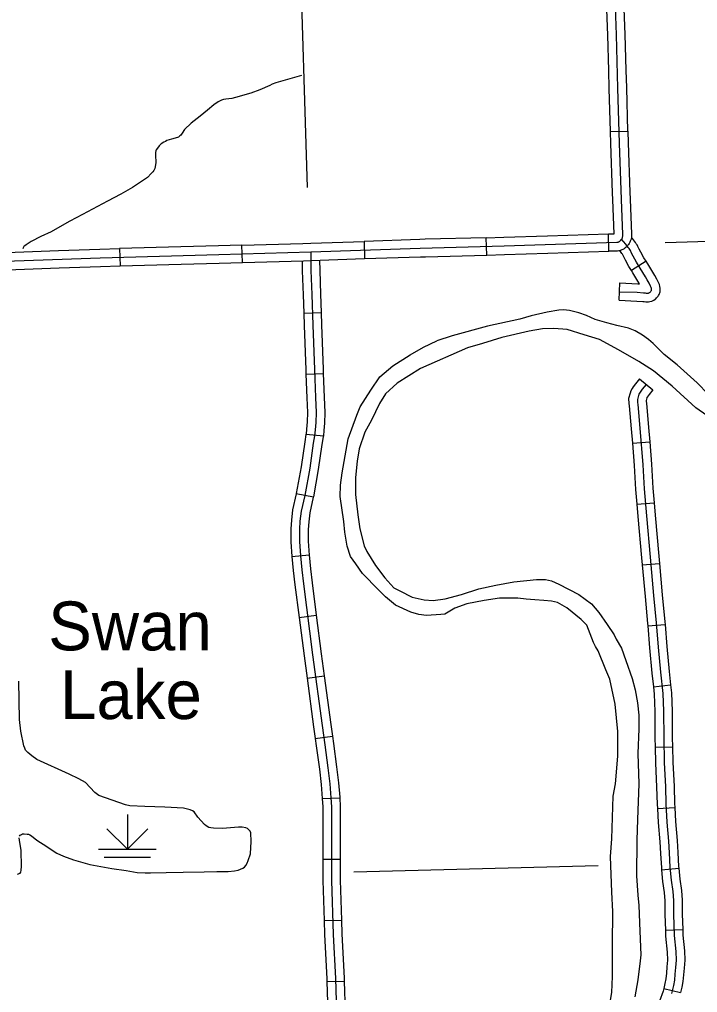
# Model space of a CAD drawing. Extents: x 1720274 to 1751788, y 372074 to 391887.
# Drawn here: x 1738121 to 1739046, y 375342 to 376671 of the extents above; entities that cross this region are included whole.
import ezdxf

# ---------------------------------------------------------------- set-up
doc = ezdxf.new("R2010")
doc.units = 0
for name, color, linetype in [('Level 31', 7, 'Continuous'), ('Level 32', 7, 'Continuous'), ('Level 35', 7, 'Continuous'), ('Level 44', 7, 'Continuous'), ('Level 47', 7, 'Continuous'), ('Level 5', 7, 'Continuous'), ('Level 9', 7, 'Continuous')]:
    doc.layers.add(name, color=color, linetype=linetype)

msp = doc.modelspace()

# ---------------------------------------------------------------- linework, layer by layer
at = {"layer": 'Level 31'}
for p, q in [((1738927.4, 376517.8), (1738951.1, 376518.4)), ((1738758.5, 376349.2), (1738757.9, 376372.9)), ((1738925.3, 376354.4), (1738924.6, 376378.1)), ((1738425, 376339.1), (1738424.3, 376362.8)), ((1738591, 376367.9), (1738591.8, 376344.3)), ((1738257.5, 376358.1), (1738258.2, 376334.4)), ((1738258.2, 376334.4), (1738258.2, 376334.4)), ((1738591.8, 376344.3), (1738591.8, 376344.3))]:
    msp.add_line(p, q, dxfattribs=at)
for points in [[(1738942.4, 376370.7), (1738942.6, 376370.9), (1738943, 376371.5), (1738943.3, 376371.9), (1738943.6, 376372.6), (1738943.8, 376373.1), (1738944, 376373.9), (1738944.2, 376374.8), (1738944.2, 376375.6), (1738944.2, 376377.2), (1738942.5, 376425), (1738939.8, 376501.9), (1738937.6, 376577.2), (1738935.7, 376650.1), (1738933.7, 376701.6), (1738933.4, 376704), (1738933.2, 376706), (1738933, 376707.8), (1738932.7, 376710), (1738932.3, 376712.2), (1738931.7, 376714.6), (1738930.9, 376717.1), (1738930.6, 376718.4)], [(1738925.1, 376601.2), (1738923.9, 376649.7), (1738922.5, 376684.4)], [(1738948.8, 376601.8), (1738947.5, 376650.5), (1738946.2, 376685.3)], [(1738927.4, 376517.8), (1738925.8, 376576.9), (1738925.1, 376601.2)], [(1738951.1, 376518.4), (1738949.5, 376577.5), (1738948.8, 376601.8)], [(1738930.3, 376434.3), (1738927.9, 376501.5), (1738927.4, 376517.8)], [(1738951.1, 376518.4), (1738951.6, 376502.3), (1738954, 376435.1)], [(1738924.6, 376378.1), (1738932.3, 376378.3), (1738930.6, 376424.6), (1738930.3, 376434.3)], [(1738954, 376435.1), (1738954.3, 376425.4), (1738956, 376377.6), (1738956.1, 376375.4), (1738956, 376373.4), (1738955.6, 376371.1), (1738954.9, 376368.9), (1738954.4, 376368), (1738954, 376366.9), (1738953.1, 376365.2), (1738951.9, 376363.5), (1738951.2, 376362.7), (1738951.1, 376362.6), (1738951, 376362.5), (1738950.4, 376361.8), (1738949, 376360.2), (1738947.6, 376359), (1738946, 376357.8), (1738944.2, 376356.9), (1738942.9, 376356.2), (1738942.1, 376355.9), (1738941.2, 376355.5), (1738940.6, 376355.4), (1738940, 376355.2), (1738938.7, 376354.9), (1738936.9, 376354.7), (1738925.3, 376354.4)], [(1738757.9, 376372.9), (1738674.5, 376370.7)], [(1738757.9, 376372.9), (1738781.9, 376373.6), (1738841.2, 376375.4)], [(1738841.2, 376375.4), (1738924.6, 376378.1)], [(1738340.9, 376360.5), (1738257.5, 376358.1)], [(1738424.3, 376362.8), (1738392.4, 376361.9), (1738340.9, 376360.5)], [(1738424.3, 376362.8), (1738507.7, 376365.2)], [(1738507.7, 376365.2), (1738518.2, 376365.5), (1738591, 376367.9)], [(1738518.5, 376353.7), (1738667.7, 376358.7), (1738782.2, 376361.7), (1738936.1, 376366.6), (1738936.8, 376366.6)], [(1738674.5, 376370.7), (1738667.3, 376370.5), (1738591, 376367.9)], [(1738936.8, 376366.6), (1738937.1, 376366.7), (1738937.3, 376366.8), (1738937.5, 376366.8), (1738937.7, 376366.9), (1738938.1, 376367.1), (1738938.9, 376367.4), (1738939.6, 376367.8), (1738940.2, 376368.2), (1738940.7, 376368.7), (1738941.4, 376369.4), (1738941.7, 376369.9), (1738942.1, 376370.4), (1738942.4, 376370.7)], [(1737257.5, 376308.3), (1737305.2, 376310.2), (1737378.2, 376313.6), (1737446.6, 376316.8), (1737514.4, 376319.4), (1737666.2, 376325.4), (1737815.1, 376331.2), (1737916, 376335.2), (1738087.5, 376340.4), (1738231, 376345.5), (1738392.8, 376350.1), (1738518.5, 376353.7)], [(1738090.7, 376352.4), (1738174.1, 376355.3)], [(1738174.1, 376355.3), (1738230.6, 376357.4), (1738257.5, 376358.1)], [(1738591.8, 376344.3), (1738668, 376346.8), (1738675.1, 376347)], [(1738675.1, 376347), (1738758.5, 376349.2)], [(1738758.5, 376349.2), (1738782.6, 376349.9), (1738842, 376351.7)], [(1738842, 376351.7), (1738925.3, 376354.4)], [(1738174.9, 376331.7), (1738231.3, 376333.7), (1738258.2, 376334.4)], [(1738258.2, 376334.4), (1738341.6, 376336.8)], [(1738341.6, 376336.8), (1738393.1, 376338.2), (1738425, 376339.1)], [(1738425, 376339.1), (1738508.4, 376341.5)], [(1738508.4, 376341.5), (1738518.9, 376341.8), (1738591.8, 376344.3)], [(1738091.6, 376328.7), (1738174.9, 376331.7)]]:
    msp.add_lwpolyline(points, dxfattribs=at)
at = {"layer": 'Level 32'}
for p, q in [((1738975.9, 376340.8), (1738956, 376328)), ((1738939.2, 376287.4), (1738940.1, 376311.1)), ((1738508.9, 376269.9), (1738532.5, 376270.7)), ((1738511.7, 376186.5), (1738535.4, 376187.3)), ((1738967.2, 376180.2), (1738985.3, 376165)), ((1738511.9, 376104.7), (1738535.5, 376102.4)), ((1738957.3, 376092.2), (1738981, 376094.1)), ((1738498.6, 376023.4), (1738521.9, 376019.2)), ((1738963.2, 376009), (1738986.9, 376010.9)), ((1738492.5, 375937.4), (1738516.1, 375939.7)), ((1738970.8, 375925.9), (1738994.4, 375927.9)), ((1738502.3, 375854.2), (1738525.8, 375857.2)), ((1738978.3, 375842.8), (1739001.9, 375844.8)), ((1738513.2, 375771.4), (1738536.7, 375774.6)), ((1738985.9, 375759.5), (1739009.5, 375762)), ((1738524.4, 375688.7), (1738547.9, 375692)), ((1738988.4, 375677.1), (1739012.1, 375677.6)), ((1738534.1, 375607), (1738557.8, 375608.1)), ((1738991.5, 375593.4), (1739015.2, 375594.6)), ((1738534.8, 375524.1), (1738558.5, 375524.1)), ((1738997, 375509.6), (1739020.6, 375512)), ((1738536.5, 375440.4), (1738560.2, 375441)), ((1739002.3, 375427.3), (1739026, 375428)), ((1738540.2, 375357), (1738563.9, 375357.7)), ((1739000, 375347.6), (1739023, 375341.9))]:
    msp.add_line(p, q, dxfattribs=at)
for points in [[(1738975.9, 376340.8), (1738972.9, 376345.4), (1738968.9, 376353.1), (1738966.7, 376357.3), (1738964.9, 376361.1), (1738963.6, 376363.3), (1738962.6, 376364.7), (1738961.5, 376366.3), (1738960.3, 376368), (1738957.5, 376371.6), (1738955.9, 376373.3)], [(1738939.6, 376299.2), (1738963.9, 376298.3), (1738972.4, 376297.6), (1738974.6, 376297.4), (1738976.3, 376297.2), (1738977.1, 376297.2), (1738977.9, 376297.3), (1738978.5, 376297.3), (1738979.1, 376297.3), (1738979.9, 376297.5), (1738980.4, 376297.7), (1738980.8, 376298), (1738981.4, 376298.6), (1738982, 376299.1), (1738982.6, 376299.8), (1738983, 376300.3), (1738983.2, 376300.7), (1738983.4, 376301.3), (1738983.4, 376301.7), (1738983.4, 376302.2), (1738983.4, 376302.7), (1738983.3, 376303.6), (1738982.9, 376304.8), (1738982.1, 376306.7), (1738980, 376310.8), (1738977.6, 376315.5), (1738975, 376319.6), (1738968.1, 376331.1), (1738962.7, 376339.4), (1738958.4, 376347.6), (1738956.1, 376352), (1738954.5, 376355.4), (1738953.7, 376356.7), (1738952.8, 376358), (1738951.7, 376359.6), (1738950.8, 376361), (1738948.4, 376363.9), (1738945.1, 376367.5), (1738942.4, 376370.7)], [(1738518.5, 376353.7), (1738518.6, 376328), (1738519.8, 376295.2), (1738521.3, 376253.4), (1738523.3, 376192.8), (1738524.7, 376154.5), (1738525.7, 376134.1), (1738525.1, 376120.5)], [(1738956, 376328), (1738952.5, 376333.4), (1738947.9, 376342.1), (1738945.5, 376346.8), (1738944.1, 376349.7), (1738943.8, 376350.2), (1738943.1, 376351.2), (1738942, 376352.8), (1738941.2, 376353.9), (1738940.1, 376355.3)], [(1738506.7, 376341.5), (1738506.8, 376327.8), (1738508, 376294.8), (1738508.9, 376269.9)], [(1738530.4, 376342.2), (1738530.5, 376328.2), (1738531.7, 376295.7), (1738532.5, 376270.7)], [(1738939.2, 376287.4), (1738963.2, 376286.4), (1738971.4, 376285.8), (1738973.5, 376285.6), (1738975.7, 376285.4), (1738977.5, 376285.4), (1738978.3, 376285.4), (1738979.1, 376285.4), (1738980.9, 376285.6), (1738983.6, 376286.1), (1738986.4, 376287.4), (1738988.4, 376288.9), (1738989.2, 376289.6), (1738990.4, 376290.7), (1738992.3, 376292.9), (1738992.9, 376293.8), (1738994, 376295.4), (1738995, 376298.8), (1738995.3, 376301), (1738995.3, 376302.2), (1738995.3, 376303.8), (1738994.8, 376306.4), (1738994.1, 376308.8), (1738992.9, 376311.6), (1738990.6, 376316.2), (1738987.9, 376321.5), (1738985, 376325.9), (1738978.2, 376337.3), (1738975.9, 376340.8)], [(1738940.1, 376311.1), (1738964.6, 376310.1), (1738967.1, 376309.9), (1738964.9, 376313.4), (1738958, 376324.8), (1738956, 376328)], [(1738508.9, 376269.9), (1738509.5, 376253), (1738511.5, 376192.4), (1738511.7, 376186.5)], [(1738532.5, 376270.7), (1738533.1, 376253.8), (1738535.2, 376193.3), (1738535.4, 376187.3)], [(1738535.4, 376187.3), (1738536.5, 376155), (1738537.6, 376134.2), (1738536.9, 376119.8), (1738536.2, 376109.6), (1738535.5, 376102.4)], [(1738511.7, 376186.5), (1738512.9, 376154), (1738513.9, 376134.1), (1738513.3, 376121.2), (1738512.6, 376111.6), (1738511.9, 376104.7)], [(1738967.2, 376180.2), (1738961.4, 376173.4), (1738958.3, 376169.1), (1738956.8, 376167.1), (1738955, 376163.7), (1738954.2, 376160.8), (1738952.2, 376153.3), (1738952.4, 376146.4), (1738953.1, 376143.3), (1738955.7, 376111.9), (1738957.3, 376092.2)], [(1738976.2, 376172.6), (1738970.8, 376166.1), (1738967.8, 376162.1), (1738966.9, 376160.8), (1738966.1, 376159.3), (1738965.6, 376157.6), (1738964.1, 376151.9), (1738964.2, 376147.9), (1738964.9, 376145.1), (1738967.5, 376112.9), (1738971.6, 376062.6), (1738973.4, 376029.9), (1738976.4, 375992.9), (1738981.7, 375936.7), (1738986.3, 375884.1), (1738989.9, 375847.1), (1738992.6, 375813.6), (1738995.7, 375779.4), (1738998.8, 375750.2), (1738999.8, 375726.1), (1739000, 375690), (1739000.7, 375656.2), (1739002.3, 375623), (1739003, 375599.5), (1739004.3, 375574.8), (1739006.4, 375548.8), (1739007.7, 375532.7), (1739008.6, 375513), (1739010.4, 375495.2), (1739012.5, 375480), (1739013.4, 375467.6), (1739013.4, 375448.6), (1739014.4, 375419.8), (1739016.4, 375398.1), (1739016.9, 375386.2), (1739016.3, 375376), (1739015.4, 375367.1), (1739014.6, 375358.7), (1739013.2, 375351.6), (1739010.5, 375340.6)], [(1738985.3, 376165), (1738980.1, 376158.7), (1738977.3, 376155), (1738977.1, 376154.7), (1738977, 376154.4), (1738976, 376150.6), (1738976, 376149.4), (1738976.6, 376146.8), (1738979.3, 376113.9), (1738981, 376094.1)], [(1738525.1, 376120.5), (1738524.4, 376110.6), (1738523.6, 376102.5), (1738521.8, 376092.2), (1738516.9, 376058.2), (1738510.2, 376020.9), (1738505.3, 375999.3), (1738503.6, 375985.8), (1738502.9, 375974.8), (1738503, 375958.1), (1738504.3, 375938.6), (1738506.1, 375919.5), (1738508.3, 375900.1), (1738520.9, 375803.2), (1738533.9, 375706.6), (1738537.6, 375680.3), (1738541.8, 375648.7), (1738544.3, 375627.1), (1738545.9, 375607.8), (1738546.5, 375595.8), (1738546.4, 375584.3), (1738546.5, 375561), (1738546.7, 375535.6), (1738546.7, 375513), (1738546.8, 375495.1), (1738548.9, 375421.4), (1738551.9, 375361.1), (1738553.3, 375315.1)], [(1738511.9, 376104.7), (1738511.8, 376104.1), (1738510.1, 376094), (1738505.2, 376060.1), (1738498.6, 376023.4)], [(1738535.5, 376102.4), (1738535.3, 376101), (1738533.6, 376090.3), (1738528.6, 376056.3), (1738521.9, 376019.2)], [(1738981, 376094.1), (1738983.5, 376063.4), (1738985.3, 376030.7), (1738986.9, 376010.9)], [(1738957.3, 376092.2), (1738959.8, 376061.8), (1738961.6, 376029.1), (1738963.2, 376009)], [(1738498.6, 376023.4), (1738498.6, 376023.2), (1738493.6, 376001.3), (1738491.8, 375986.9), (1738491.1, 375975.2), (1738491.2, 375957.7), (1738492.4, 375937.6), (1738492.5, 375937.4)], [(1738521.9, 376019.2), (1738521.8, 376018.5), (1738517, 375997.2), (1738515.5, 375984.7), (1738514.8, 375974.5), (1738514.9, 375958.5), (1738516.1, 375939.5), (1738516, 375939.7)], [(1738963.2, 376009), (1738964.6, 375991.9), (1738969.9, 375935.7), (1738970.8, 375925.9)], [(1738986.9, 376010.9), (1738988.2, 375993.9), (1738993.5, 375937.8), (1738994.4, 375927.9)], [(1738492.5, 375937.4), (1738494.3, 375918.2), (1738496.5, 375898.7), (1738502.3, 375854.2)], [(1738516.1, 375939.7), (1738517.8, 375920.7), (1738520.1, 375901.6), (1738525.8, 375857.2)], [(1738970.8, 375925.9), (1738974.5, 375883), (1738978.1, 375846), (1738978.3, 375842.8)], [(1738994.4, 375927.9), (1738998.1, 375885.2), (1739001.7, 375848.2), (1739001.9, 375844.8)], [(1738525.8, 375857.2), (1738532.6, 375804.7), (1738536.7, 375774.6)], [(1738502.3, 375854.2), (1738509.1, 375801.6), (1738513.2, 375771.4)], [(1738978.3, 375842.8), (1738980.8, 375812.6), (1738983.9, 375778.2), (1738985.9, 375759.5)], [(1739001.9, 375844.8), (1739004.5, 375814.6), (1739007.5, 375780.5), (1739009.5, 375762)], [(1738536.7, 375774.6), (1738545.6, 375708.2), (1738547.9, 375692)], [(1738513.2, 375771.4), (1738522.2, 375705), (1738524.4, 375688.7)], [(1739009.5, 375762), (1739010.6, 375751.1), (1739011.7, 375726.3), (1739011.8, 375690.2), (1739012.1, 375677.6)], [(1738985.9, 375759.5), (1738987, 375749.4), (1738988, 375725.8), (1738988.1, 375689.9), (1738988.4, 375677.1)], [(1738524.4, 375688.7), (1738525.8, 375678.7), (1738530.1, 375647.2), (1738532.5, 375626), (1738534.1, 375607), (1738534.1, 375607)], [(1738547.9, 375692), (1738549.3, 375681.9), (1738553.6, 375650.2), (1738556.1, 375628.3), (1738557.8, 375608.6), (1738557.8, 375608.1)], [(1738988.4, 375677.1), (1738988.8, 375655.7), (1738990.4, 375622.6), (1738991.2, 375599), (1738991.5, 375593.4)], [(1739012.1, 375677.6), (1739012.5, 375656.6), (1739014.1, 375623.5), (1739014.9, 375600), (1739015.2, 375594.6)], [(1738534.1, 375607), (1738534.7, 375595.6), (1738534.6, 375584.3), (1738534.7, 375560.9), (1738534.8, 375535.6), (1738534.8, 375524.1)], [(1738557.8, 375608.1), (1738558.4, 375596.1), (1738558.3, 375584.3), (1738558.4, 375561), (1738558.5, 375535.7), (1738558.5, 375524.1)], [(1738991.5, 375593.4), (1738992.5, 375574), (1738994.6, 375547.9), (1738995.8, 375531.9), (1738996.8, 375512.2), (1738997, 375509.6)], [(1739015.2, 375594.6), (1739016.1, 375575.5), (1739018.3, 375549.8), (1739019.5, 375533.4), (1739020.4, 375513.9), (1739020.6, 375512)], [(1738534.8, 375524.1), (1738534.8, 375512.9), (1738534.9, 375494.9), (1738536.5, 375440.4)], [(1738558.5, 375524.1), (1738558.5, 375513), (1738558.6, 375495.4), (1738560.2, 375441)], [(1738997, 375509.6), (1738998.6, 375493.8), (1739000.7, 375478.7), (1739001.5, 375467.2), (1739001.6, 375448.4), (1739002.3, 375427.3)], [(1739020.6, 375512), (1739022.1, 375496.6), (1739024.3, 375481.2), (1739025.2, 375468), (1739025.3, 375448.9), (1739026, 375428)], [(1738536.5, 375440.4), (1738537, 375421), (1738540.1, 375360.6), (1738540.2, 375357)], [(1738560.2, 375441), (1738560.7, 375421.9), (1738563.8, 375361.6), (1738563.9, 375357.7)], [(1739002.3, 375427.3), (1739002.5, 375419.1), (1739004.6, 375397.2), (1739005.1, 375386.2), (1739004.5, 375376.9), (1739003.7, 375368.3), (1739002.8, 375360.5), (1739001.6, 375354.2), (1739000, 375347.6)], [(1739026, 375428), (1739026.2, 375420.5), (1739028.2, 375398.9), (1739028.8, 375386.1), (1739028.1, 375375.1), (1739027.2, 375365.9), (1739026.3, 375357), (1739024.8, 375349.1), (1739023, 375341.9)], [(1738540.2, 375357), (1738541.5, 375314.7), (1738543.3, 375273.5)], [(1738563.9, 375357.7), (1738565.2, 375315.6), (1738567, 375274.5)], [(1739000, 375347.6), (1738999.1, 375344), (1738994.2, 375330.2), (1738988.2, 375317.7), (1738982.2, 375302.6), (1738978.6, 375292.6), (1738973.8, 375279.2), (1738970.5, 375272)]]:
    msp.add_lwpolyline(points, dxfattribs=at)
at = {"layer": 'Level 35'}
msp.add_lwpolyline([(1738505.7, 376594.4), (1738489.9, 376589.9), (1738470.5, 376584.3), (1738465.8, 376582.6), (1738462.6, 376580.8), (1738449, 376575), (1738436.5, 376570.5), (1738415.4, 376564.4), (1738410.8, 376563.1), (1738406.5, 376562.7), (1738402.2, 376562.3), (1738399.2, 376561.8), (1738396.4, 376560.8), (1738391.9, 376558.4), (1738386, 376554.3), (1738377.2, 376547), (1738367.5, 376539), (1738355.2, 376529.3), (1738346.2, 376520.8), (1738342.7, 376515.7), (1738341.1, 376513.1), (1738339.8, 376511.9), (1738338.8, 376511.1), (1738337.7, 376510.4), (1738336.4, 376509.7), (1738328.3, 376507.4), (1738321.8, 376505.5), (1738320.1, 376504.5), (1738317.9, 376503.5), (1738314.2, 376501), (1738311.4, 376498.5), (1738309.1, 376495.4), (1738307.4, 376492.9), (1738306.8, 376491.4), (1738306.4, 376489.1), (1738306.2, 376486.3), (1738306.7, 376475.1), (1738305.7, 376467.5), (1738304.2, 376464.6), (1738302.7, 376462.7), (1738300.7, 376460.5), (1738295.3, 376455), (1738291.6, 376452.2), (1738275.1, 376441.6), (1738259.2, 376432.5), (1738240.7, 376422.8), (1738206.9, 376404.5), (1738189.7, 376395.5), (1738182.2, 376391.5), (1738163.8, 376380.8), (1738150, 376374.6), (1738136.8, 376367.8), (1738129.8, 376363.3), (1738128.1, 376362), (1738126.9, 376360.7), (1738126, 376359.3), (1738125.5, 376357.9)], dxfattribs=at)
at = {"layer": 'Level 44'}
for p, q in [((1738268, 375585), (1738268, 375537.6)), ((1738268, 375537.6), (1738240.1, 375565.6)), ((1738268, 375537.6), (1738296, 375565.6)), ((1738228.5, 375537.6), (1738307.5, 375537.6)), ((1738236.4, 375526.9), (1738299.6, 375526.9))]:
    msp.add_line(p, q, dxfattribs=at)
at = {"layer": 'Level 47'}
for points in [[(1738120.7, 375555.3), (1738121.6, 375556.7), (1738123.3, 375557.9), (1738125, 375558.5), (1738127.3, 375558.6), (1738131.1, 375558.3), (1738133.2, 375558.2), (1738134.8, 375557.5), (1738137.2, 375555.8), (1738144.3, 375550), (1738158.1, 375541.2), (1738165.2, 375536.4), (1738171.7, 375532.5), (1738181, 375528.1), (1738194.7, 375523.3), (1738216.7, 375516.9), (1738246.7, 375511.3), (1738266.4, 375508.6), (1738281.6, 375506.1), (1738292.4, 375505.5), (1738299.8, 375505.3), (1738321, 375505.9), (1738344.2, 375506.4), (1738373, 375506.8), (1738390.3, 375507.4), (1738405.6, 375507.2), (1738414.1, 375508.2), (1738419.1, 375509.2), (1738422.4, 375510.5), (1738425.5, 375511.9), (1738427.8, 375513.2), (1738429.9, 375515.3), (1738431.7, 375518.6), (1738433, 375522.1), (1738436.1, 375531.6), (1738437.1, 375548.2), (1738436.3, 375560.2), (1738435.5, 375562.5), (1738434, 375564), (1738431.9, 375565.8), (1738429.5, 375566.9), (1738424.5, 375567.7), (1738419.7, 375567.7), (1738397.9, 375566), (1738385.5, 375566.4), (1738382, 375566.8), (1738379.3, 375567.3), (1738375.5, 375569.5), (1738373.2, 375571.6), (1738364.3, 375581.6), (1738359.1, 375588.8), (1738357.1, 375590.1), (1738353.6, 375591.3), (1738344.8, 375593.6), (1738319.1, 375595), (1738291.9, 375595.9), (1738271.4, 375597.1), (1738265.6, 375598.1), (1738229.1, 375611.2), (1738223.7, 375615.3), (1738210.8, 375628.8), (1738201.6, 375633.6), (1738188.8, 375640.2), (1738144.3, 375660.3), (1738137.6, 375665.1), (1738132.3, 375669.6), (1738129.2, 375673.1), (1738127.9, 375675.7), (1738126.7, 375679), (1738122.7, 375699.1), (1738120.9, 375714.7), (1738119.9, 375767.3)], [(1738118.1, 375503.7), (1738121.5, 375505), (1738122.4, 375506.3), (1738123.2, 375509.1), (1738123.4, 375514.2), (1738123, 375535.9), (1738120.9, 375550.1), (1738120.4, 375553.3)]]:
    msp.add_lwpolyline(points, dxfattribs=at)
at = {"layer": 'Level 5'}
for points in [[(1738503.1, 376782.3), (1738513.2, 376441.6)], [(1739002.1, 376366.2), (1739374.5, 376377.7)], [(1738577.2, 375506.7), (1738910.5, 375515.3)]]:
    msp.add_lwpolyline(points, dxfattribs=at)
at = {"layer": 'Level 9'}
for points in [[(1739060.8, 376159.1), (1739045.5, 376174.8), (1739018.6, 376199.5), (1739000.6, 376213.6), (1738985.8, 376228.2), (1738979.1, 376234.1), (1738971, 376240), (1738961.3, 376245.6), (1738952.2, 376249.4), (1738936, 376253.2), (1738922.3, 376256.6), (1738906.7, 376261.4), (1738894.6, 376266.6), (1738884.4, 376270.3), (1738871.4, 376273.6), (1738863.4, 376274.4), (1738856.7, 376273.8), (1738840.8, 376271.1), (1738819.3, 376266.1), (1738803.6, 376261.7), (1738759.5, 376252), (1738711.2, 376239.1), (1738690.5, 376232.2)], [(1739069.4, 376122.7), (1739044, 376140.6), (1739011.7, 376170.2), (1738986.1, 376190.9), (1738965.9, 376204), (1738938.2, 376219.6), (1738912.4, 376233.8), (1738891.4, 376240.2), (1738868.1, 376247.5), (1738850.2, 376249), (1738834.8, 376248.6), (1738816.6, 376245.2), (1738779, 376236.7), (1738752.7, 376228.6), (1738732.3, 376222.5), (1738668, 376194.4), (1738636.4, 376174.4), (1738620.3, 376159.6), (1738612.2, 376146.3), (1738601, 376123.8), (1738592.2, 376107.1), (1738584.3, 376084.6), (1738581.8, 376067.5), (1738579.5, 376045.4), (1738579.3, 376022.3), (1738582.7, 375994.6), (1738585.4, 375975.2), (1738591.4, 375952), (1738594.9, 375944.5), (1738606.6, 375925.2), (1738619.5, 375908.3)], [(1738907, 375814.6), (1738904.2, 375820.2), (1738899.6, 375831.7), (1738895, 375843.7), (1738887.3, 375851.4), (1738867.6, 375867.4), (1738855, 375874.5), (1738846.8, 375876.6), (1738836.4, 375877.2), (1738824.3, 375878.3), (1738812.3, 375879.1), (1738800.8, 375880.4), (1738776.1, 375880.8), (1738755, 375877.4), (1738731.5, 375872.7), (1738714.9, 375866.8), (1738701.3, 375858.7), (1738695.7, 375858.1), (1738676.5, 375857), (1738665.7, 375858.1), (1738654.9, 375861.6), (1738634.1, 375871.2), (1738620.1, 375882.4), (1738610.6, 375891.8), (1738589.1, 375914.5), (1738579.7, 375927.7), (1738572.5, 375937.5), (1738567.9, 375951.6), (1738564.8, 375970.6), (1738563.3, 375985.2), (1738558.3, 376019.4), (1738558.9, 376035), (1738561.2, 376051.7), (1738569.5, 376098.3), (1738581.4, 376130.6), (1738585.8, 376141.9), (1738600.4, 376164.6), (1738612.8, 376183.1), (1738630.3, 376197.9), (1738653.9, 376212.9), (1738672.4, 376223.6), (1738690.5, 376232.2)], [(1738619.5, 375908.3), (1738631.6, 375894.7), (1738639.7, 375890.6), (1738656.6, 375882), (1738673, 375878.5), (1738685.3, 375877.4), (1738701.7, 375879.5), (1738724.2, 375885.4), (1738747.9, 375893.3), (1738770.8, 375898.5), (1738795.6, 375902.7), (1738826.2, 375906), (1738838.9, 375906), (1738846.8, 375904.3), (1738857, 375899.5), (1738884.1, 375885.6), (1738901.4, 375872.7), (1738911.4, 375861.2), (1738923, 375844.6), (1738932.3, 375830.4), (1738935.1, 375824.4)], [(1738927.4, 375331.3), (1738929.3, 375342.1), (1738930.3, 375363.8), (1738930.3, 375407.4), (1738930.8, 375452.4), (1738929.1, 375479), (1738927.4, 375527.8), (1738929.1, 375551.8), (1738931.2, 375610.1), (1738934.3, 375627.2), (1738937.6, 375664.7), (1738937.6, 375698.7), (1738933.9, 375735.8), (1738926.4, 375769.9), (1738921.2, 375782.6), (1738910.8, 375808.7), (1738907, 375814.6)], [(1738935.1, 375824.4), (1738942.3, 375812.3), (1738948.3, 375795.4), (1738957.2, 375771), (1738961.2, 375755.4), (1738964.1, 375737.5), (1738966.2, 375721), (1738966.2, 375702), (1738964.9, 375668.5), (1738966, 375626.8), (1738964.3, 375578.1), (1738963.3, 375550.1), (1738963.1, 375501.4), (1738964.7, 375475.1), (1738966.2, 375460.9), (1738967.4, 375425.9), (1738968.9, 375393.4), (1738967.7, 375385.1), (1738964.7, 375359.3), (1738960.6, 375336.1)]]:
    msp.add_lwpolyline(points, dxfattribs=at)

# ---------------------------------------------------------------- texts
at = {"layer": 'Level 35'}
for s, p in [('Swan', (1738160, 375809.3)), ('Lake', (1738176.2, 375715.5))]:
    msp.add_text(s, height=66.74, dxfattribs=at).set_placement(p)

doc.saveas('drawing.dxf')
